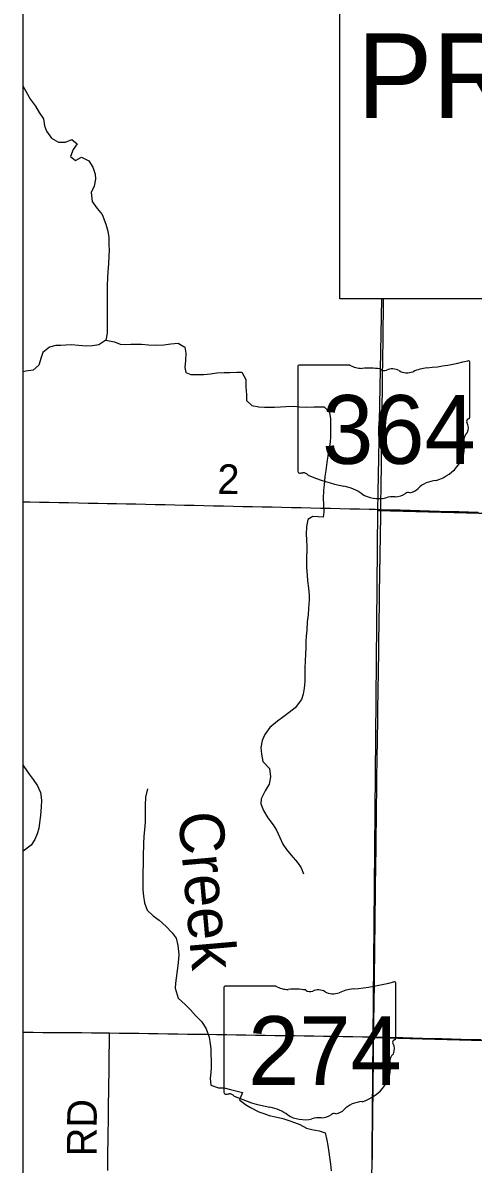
# Model space of a CAD drawing. Extents: x 0 to 34, y 0 to 22.
# Drawn here: x 2.1 to 2.963, y 17.239 to 19.428 of the extents above; entities that cross this region are included whole.
import ezdxf

# ---------------------------------------------------------------- set-up
doc = ezdxf.new("R2010")
doc.units = 0
for name, color, linetype in [('GM_X_Corporation', 7, 'Continuous'), ('GM_X_County_Road', 7, 'Continuous'), ('GM_X_County_Road_Text', 7, 'Continuous'), ('GM_X_Minor_River', 7, 'Continuous'), ('GM_X_Minor_River_Text', 7, 'Continuous'), ('GM_X_State_Location', 7, 'Continuous'), ('GM_X_State_Route', 7, 'Continuous'), ('GM_X_State_Shield', 7, 'Continuous'), ('GM_X_Township_Road', 7, 'Continuous'), ('GM_X_Township_Road_Text', 7, 'Continuous'), ('SH_Text', 7, 'Continuous')]:
    doc.layers.add(name, color=color, linetype=linetype)

msp = doc.modelspace()

# ---------------------------------------------------------------- linework, layer by layer
at = {"layer": 'GM_X_Corporation'}
for points in [[(8.9, 20.9), (2.1, 20.9), (2.1, 14.1), (7.7244, 14.1)], [(3.5996, 19.4692), (2.7976, 19.484), (2.7779, 19.4843), (2.1, 19.4964), (2.1, 16.485), (2.253, 16.4822), (2.4333, 16.478), (2.4403, 16.4778), (2.5826, 16.473), (2.7595, 16.4724), (3.1897, 16.4617), (3.4295, 16.4557), (3.687, 16.4502), (3.6948, 16.4501), (3.7682, 16.4494), (4.2697, 16.4379), (4.8738, 16.4249)], [(3.7979, 18.8986), (3.7969, 18.4658), (2.7802, 18.4929), (2.7874, 18.8986)]]:
    msp.add_lwpolyline(points, dxfattribs=at)
for points in [[(3.7969, 18.4658), (3.785, 17.4549), (2.771, 17.4824), (2.7802, 18.4929)], [(3.785, 17.4549), (3.7672, 16.4521), (2.7618, 16.4707), (2.771, 17.4824)]]:
    msp.add_lwpolyline(points, close=True, dxfattribs=at)
at = {"layer": 'GM_X_County_Road'}
msp.add_lwpolyline([(2.1, 18.5096), (2.1132, 18.5094), (2.1318, 18.509), (2.1504, 18.5086), (2.1691, 18.5082), (2.1877, 18.5079), (2.2063, 18.5075), (2.225, 18.5071), (2.2436, 18.5068), (2.2614, 18.5064), (2.2791, 18.5061), (2.2977, 18.5057), (2.3164, 18.5052), (2.335, 18.5048), (2.3537, 18.5044), (2.3723, 18.504), (2.3909, 18.5036), (2.4096, 18.5032), (2.4282, 18.5028), (2.4468, 18.5024), (2.4655, 18.502), (2.4841, 18.5016), (2.5027, 18.5011), (2.5214, 18.5007), (2.54, 18.5003), (2.5586, 18.4999), (2.5773, 18.4995), (2.5959, 18.4991), (2.6145, 18.4987), (2.6332, 18.4983), (2.6518, 18.4979), (2.6704, 18.4974), (2.6891, 18.497), (2.7077, 18.4966), (2.7263, 18.4962), (2.745, 18.4958), (2.7636, 18.4954), (2.7747, 18.4951), (2.7858, 18.4949), (2.8044, 18.4943), (2.823, 18.4938), (2.8417, 18.4933), (2.8603, 18.4927), (2.8789, 18.4922), (2.8976, 18.4916), (2.9162, 18.4911), (2.9349, 18.4906), (2.9535, 18.49), (2.9721, 18.4895)], dxfattribs=at)
at = {"layer": 'GM_X_Minor_River'}
for points in [[(2.1, 19.3067), (2.1065, 19.2954), (2.1145, 19.2808), (2.1241, 19.268), (2.1314, 19.2561), (2.1395, 19.2434), (2.1414, 19.23), (2.145, 19.2201), (2.1546, 19.2066), (2.1684, 19.199), (2.1817, 19.1987), (2.194, 19.2041), (2.204, 19.1959), (2.1962, 19.1847), (2.1913, 19.1712), (2.201, 19.1641), (2.2126, 19.1703), (2.2264, 19.1631), (2.2341, 19.1512), (2.2388, 19.1378), (2.2389, 19.1279), (2.2367, 19.1146), (2.2311, 19.1022), (2.2326, 19.0855), (2.2426, 19.072), (2.2518, 19.06), (2.259, 19.0419), (2.2625, 19.0282), (2.2645, 19.0164)], [(2.2645, 19.0164), (2.2649, 19.0019), (2.2651, 18.992), (2.2648, 18.9814), (2.2641, 18.9658), (2.2626, 18.9507), (2.262, 18.9389), (2.2613, 18.9249), (2.2613, 18.9085), (2.2614, 18.8964), (2.2614, 18.8796), (2.2616, 18.8698), (2.2617, 18.8572), (2.2614, 18.8458), (2.2615, 18.8329), (2.2589, 18.8193), (2.2458, 18.8101), (2.2333, 18.8085), (2.2219, 18.8076), (2.2064, 18.8091), (2.1935, 18.8101), (2.1825, 18.8096), (2.173, 18.8091), (2.1635, 18.8089), (2.1509, 18.8062), (2.1385, 18.7958), (2.1349, 18.786), (2.1308, 18.7717), (2.1199, 18.7617), (2.1059, 18.7601), (2.1, 18.7589)], [(2.2589, 18.8193), (2.2756, 18.8162), (2.2865, 18.8118), (2.2971, 18.8112), (2.3066, 18.8114), (2.3168, 18.8119), (2.327, 18.8116), (2.341, 18.8102), (2.3532, 18.8095), (2.3699, 18.8103), (2.3832, 18.8123), (2.3973, 18.8135), (2.4104, 18.8059), (2.412, 18.7941), (2.4113, 18.7801), (2.4103, 18.7672), (2.4119, 18.7576), (2.4217, 18.7536), (2.4316, 18.7534), (2.4464, 18.7538), (2.4597, 18.755), (2.4715, 18.7567), (2.4855, 18.7571), (2.4965, 18.7572), (2.5098, 18.7581), (2.5193, 18.7582), (2.527, 18.7436), (2.5274, 18.7299), (2.5282, 18.7143), (2.5283, 18.7037), (2.5388, 18.6943), (2.552, 18.6917), (2.5626, 18.6911), (2.5728, 18.6909), (2.5823, 18.691), (2.5933, 18.6916), (2.6039, 18.6921), (2.6191, 18.6925), (2.6301, 18.6915), (2.643, 18.6908), (2.6574, 18.6916), (2.6673, 18.6918), (2.6775, 18.6912), (2.6875, 18.6807), (2.6892, 18.6688), (2.6893, 18.6571), (2.6894, 18.6472), (2.6891, 18.6339), (2.6885, 18.624), (2.6859, 18.6096), (2.6845, 18.5975), (2.6824, 18.585), (2.6801, 18.5695), (2.6783, 18.5577), (2.6769, 18.5422), (2.6759, 18.5319), (2.6755, 18.5152), (2.676, 18.5057), (2.6765, 18.4901), (2.6755, 18.4802), (2.6656, 18.4805), (2.6558, 18.4811), (2.6458, 18.4752), (2.6436, 18.4616), (2.6429, 18.4472), (2.6434, 18.4365), (2.6439, 18.4239), (2.6432, 18.3951), (2.6434, 18.3833), (2.6445, 18.3688), (2.6454, 18.3581), (2.647, 18.3437), (2.6483, 18.3307), (2.6484, 18.3208), (2.6473, 18.3053), (2.6463, 18.2927), (2.6448, 18.2791), (2.6437, 18.2631), (2.6427, 18.2517), (2.6421, 18.2415), (2.6418, 18.2282), (2.6412, 18.2183), (2.6409, 18.2031), (2.6402, 18.1914), (2.6399, 18.1777), (2.64, 18.1647), (2.639, 18.1518), (2.6372, 18.1408), (2.634, 18.1303), (2.6215, 18.1146), (2.6099, 18.1054), (2.6002, 18.0976), (2.5879, 18.0887), (2.5732, 18.0769), (2.5638, 18.0631), (2.5583, 18.0518), (2.5561, 18.0385), (2.5573, 18.0256), (2.5596, 18.0114), (2.5726, 17.9982), (2.5745, 17.9818)], [(2.1, 18.0053), (2.1016, 18.0021), (2.1122, 17.9874), (2.1196, 17.977), (2.1281, 17.965), (2.1339, 17.9523), (2.1358, 17.9375), (2.1351, 17.9245), (2.1336, 17.9082), (2.1318, 17.8938), (2.1304, 17.8832), (2.1276, 17.873), (2.1231, 17.8617), (2.1157, 17.8508), (2.1006, 17.8394), (2.1, 17.839)], [(2.5745, 17.9818), (2.572, 17.9682), (2.5641, 17.955), (2.5565, 17.9396), (2.5556, 17.9301), (2.561, 17.9175), (2.5694, 17.9036), (2.5797, 17.89), (2.5856, 17.8796), (2.5925, 17.8658), (2.5979, 17.8531), (2.6052, 17.8427), (2.6141, 17.8318), (2.6259, 17.8179), (2.6329, 17.8078), (2.6376, 17.7959)], [(2.3385, 17.9591), (2.3347, 17.9428), (2.3344, 17.9272), (2.3344, 17.912), (2.334, 17.8949), (2.3329, 17.8805), (2.3319, 17.8683), (2.3308, 17.8535), (2.3303, 17.8299), (2.3305, 17.8197), (2.3299, 17.7938), (2.3299, 17.7782), (2.33, 17.7653), (2.3309, 17.7531), (2.3333, 17.7405), (2.3383, 17.7267), (2.3494, 17.7158), (2.361, 17.7075), (2.3748, 17.6954), (2.3859, 17.683), (2.3936, 17.6726), (2.3967, 17.6588), (2.3986, 17.6413), (2.3975, 17.6253), (2.3953, 17.6105), (2.3934, 17.5961), (2.3925, 17.5866), (2.3919, 17.5768), (2.3975, 17.5576), (2.4109, 17.5455), (2.4213, 17.5354), (2.4306, 17.5245), (2.4428, 17.5121), (2.4509, 17.499), (2.457, 17.4832), (2.459, 17.4702), (2.4599, 17.4607), (2.4604, 17.4501), (2.4609, 17.4379), (2.461, 17.4249), (2.46, 17.4151), (2.459, 17.4037), (2.4602, 17.3911), (2.4745, 17.3858), (2.4859, 17.3856), (2.4976, 17.3823), (2.5108, 17.3793), (2.521, 17.3768), (2.515, 17.3629), (2.5262, 17.3538), (2.5363, 17.3479), (2.5521, 17.3399), (2.5618, 17.3363), (2.5716, 17.333), (2.5837, 17.3301), (2.5977, 17.3271), (2.6097, 17.323), (2.6203, 17.3194), (2.6304, 17.3153), (2.6432, 17.3086), (2.6533, 17.3057), (2.6673, 17.3031), (2.679, 17.2994), (2.6825, 17.2856), (2.6841, 17.2749), (2.6862, 17.2627), (2.6875, 17.2528), (2.6891, 17.2395), (2.6903, 17.2265)]]:
    msp.add_lwpolyline(points, dxfattribs=at)
at = {"layer": 'GM_X_State_Route'}
for points in [[(2.7694, 17.2383), (2.7696, 17.257), (2.7698, 17.2756), (2.77, 17.2943), (2.7702, 17.3129), (2.7704, 17.3315), (2.7706, 17.3502), (2.7708, 17.3688), (2.771, 17.3875), (2.7712, 17.4061), (2.7715, 17.4248), (2.7717, 17.4434), (2.7719, 17.462), (2.772, 17.4728), (2.7721, 17.4835), (2.7723, 17.5021), (2.7726, 17.5208), (2.7728, 17.5394), (2.773, 17.5581), (2.7733, 17.5767), (2.7735, 17.5953), (2.7737, 17.614), (2.774, 17.6326), (2.7742, 17.6513), (2.7744, 17.6699), (2.7746, 17.6885), (2.7749, 17.7072), (2.7751, 17.7258), (2.7753, 17.7445), (2.7756, 17.7631), (2.7758, 17.7818), (2.776, 17.8004), (2.7763, 17.819), (2.7765, 17.8377), (2.7767, 17.8563), (2.7769, 17.875), (2.7772, 17.8936), (2.7774, 17.9122), (2.7776, 17.9309), (2.7778, 17.9495), (2.7781, 17.9682), (2.7782, 17.9785), (2.7783, 17.9887), (2.7786, 18.0074), (2.7789, 18.026), (2.7791, 18.0447), (2.7794, 18.0633), (2.7797, 18.082), (2.78, 18.1006), (2.7802, 18.1192), (2.7805, 18.1379), (2.7808, 18.1565), (2.7811, 18.1752), (2.7813, 18.1938), (2.7816, 18.2124), (2.7819, 18.2311), (2.7822, 18.2497), (2.7824, 18.2684), (2.7827, 18.287), (2.783, 18.3056), (2.7832, 18.3243), (2.7835, 18.3429), (2.7838, 18.3616), (2.7841, 18.3802), (2.7843, 18.3988), (2.7846, 18.4175), (2.7849, 18.4361), (2.7852, 18.4548), (2.7855, 18.4734), (2.7856, 18.4842), (2.7858, 18.4949), (2.786, 18.5135), (2.7863, 18.5322), (2.7865, 18.5508), (2.7867, 18.5695), (2.787, 18.5881), (2.7872, 18.6067), (2.7875, 18.6254), (2.7877, 18.644), (2.788, 18.6627), (2.7882, 18.6813), (2.7884, 18.6999), (2.7887, 18.7186), (2.7889, 18.7372), (2.7892, 18.7559), (2.7894, 18.7745), (2.7896, 18.7931), (2.7899, 18.8118), (2.7901, 18.8304), (2.7904, 18.8491), (2.7906, 18.8677), (2.7908, 18.8864), (2.791, 18.8986)], [(2.1, 17.4923), (2.1013, 17.4923), (2.12, 17.4922), (2.1386, 17.492), (2.1572, 17.4919), (2.1759, 17.4918), (2.1945, 17.4917), (2.2132, 17.4916), (2.2318, 17.4914), (2.249, 17.4913), (2.2661, 17.4912), (2.2847, 17.4909), (2.3034, 17.4906), (2.322, 17.4904), (2.3407, 17.4901), (2.3593, 17.4898), (2.378, 17.4895), (2.3966, 17.4892), (2.4152, 17.4889), (2.4339, 17.4886), (2.4525, 17.4884), (2.4712, 17.4881), (2.4898, 17.4878), (2.5084, 17.4875), (2.5271, 17.4872), (2.5457, 17.4869), (2.5644, 17.4866), (2.583, 17.4864), (2.6016, 17.4861), (2.6203, 17.4858), (2.6389, 17.4855), (2.6576, 17.4852), (2.6762, 17.485), (2.6949, 17.4847), (2.7135, 17.4844), (2.7321, 17.4841), (2.7508, 17.4838), (2.7614, 17.4837), (2.7721, 17.4835), (2.7907, 17.483), (2.8094, 17.4825), (2.828, 17.482), (2.8467, 17.4816), (2.8653, 17.4811), (2.8839, 17.4806), (2.9026, 17.4801), (2.9212, 17.4796), (2.9398, 17.4791), (2.9585, 17.4787), (2.9771, 17.4782)]]:
    msp.add_lwpolyline(points, dxfattribs=at)
at = {"layer": 'GM_X_State_Shield'}
for p, q in [((2.9563, 18.6719), (2.9563, 18.7766)), ((2.6267, 18.7682), (2.6267, 18.5681)), ((2.7265, 18.7716), (2.63, 18.7716)), ((2.9563, 18.6719), (2.9563, 18.6719)), ((2.4851, 17.5774), (2.4851, 17.3772)), ((2.5848, 17.5808), (2.4883, 17.5808)), ((2.8147, 17.4811), (2.8147, 17.5858)), ((2.8146, 17.4811), (2.8147, 17.4811))]:
    msp.add_line(p, q, dxfattribs=at)
for centre, major_axis, start_param, end_param in [((2.8389, 19.0445), (0.3495, 0), 4.814394, 5.042369), ((2.9527, 18.777), (0.00367, 0), 6.141152, 7.989035), ((2.6305, 18.7686), (0.00382, 0), 1.712693, 3.28349), ((2.7495, 18.7949), (0.037, 0), 4.042523, 4.731795), ((2.7618, 18.6593), (0.133, 0), 1.404758, 1.657858), ((2.7919, 18.7697), (0.0107, 0), 3.836095, 5.185415), ((2.8076, 18.7465), (0.0222, 0), 0.950623, 2.079405), ((2.8363, 18.7782), (0.0267, 0), 4.081561, 5.145723), ((2.8835, 18.7105), (0.0703, 0), 1.699011, 2.107814), ((2.9555, 18.6642), (0.00568, 0), 1.883978, 3.671073), ((2.9524, 18.6715), (0.00393, 0), 5.05454, 6.418171), ((2.9193, 18.651), (0.0341, 0), 5.934695, 6.695948), ((2.8585, 18.6148), (0.0874, 0), 5.101752, 6.440018), ((2.9695, 18.6281), (0.0248, 0), 2.387724, 3.262537), ((2.6305, 18.5676), (0.00385, 0), 3.00124, 4.508301), ((2.6311, 18.5881), (0.0294, 0), 4.665946, 4.897461), ((2.6371, 18.5565), (0.0106, 0), 0.519207, 1.627899), ((2.771, 18.7363), (0.2524, 0), 4.195997, 4.488961), ((2.6957, 18.4782), (0.079, 0), 0.823519, 1.323587), ((2.8954, 18.5119), (0.0479, 0), 1.647645, 2.488434), ((2.7811, 18.5555), (0.0501, 0), 4.026481, 4.996735), ((2.8101, 18.4863), (0.0412, 0), 1.495662, 1.94098), ((2.8137, 18.5405), (0.0267, 0), 4.691044, 5.507374), ((2.8379, 18.5212), (0.00752, 0), 1.147584, 2.315152), ((2.8347, 18.5487), (0.0282, 0), 4.937069, 5.64225), ((2.4888, 17.5778), (0.00382, 0), 1.712693, 3.28349), ((2.6078, 17.604), (0.037, 0), 4.042523, 4.731795), ((2.6201, 17.4685), (0.133, 0), 1.404758, 1.657858), ((2.6503, 17.5788), (0.0107, 0), 3.836095, 5.185415), ((2.666, 17.5557), (0.0222, 0), 0.950623, 2.079405), ((2.7418, 17.5197), (0.0703, 0), 1.699011, 2.107814), ((2.6972, 17.8536), (0.3495, 0), 4.814394, 5.042369), ((2.811, 17.5862), (0.00367, 0), 6.141152, 7.989035), ((2.6946, 17.5874), (0.0267, 0), 4.081561, 5.145723), ((2.8138, 17.4734), (0.00568, 0), 1.883978, 3.671073), ((2.7777, 17.4602), (0.0341, 0), 5.934695, 6.695948), ((2.8107, 17.4807), (0.00393, 0), 5.05454, 6.418171), ((2.8278, 17.4373), (0.0248, 0), 2.387724, 3.262537), ((2.7168, 17.4239), (0.0874, 0), 5.101752, 6.440018), ((2.4889, 17.3768), (0.00385, 0), 3.00124, 4.508301), ((2.4895, 17.3973), (0.0294, 0), 4.665946, 4.897461), ((2.4955, 17.3657), (0.0106, 0), 0.519207, 1.627899), ((2.6293, 17.5455), (0.2524, 0), 4.195997, 4.488961), ((2.7537, 17.3211), (0.0479, 0), 1.647645, 2.488434), ((2.5541, 17.2873), (0.079, 0), 0.823519, 1.323587), ((2.6395, 17.3647), (0.0501, 0), 4.026481, 4.996735), ((2.6721, 17.3497), (0.0267, 0), 4.691044, 5.507374), ((2.6962, 17.3303), (0.00752, 0), 1.147584, 2.315152), ((2.693, 17.3578), (0.0282, 0), 4.937069, 5.64225), ((2.6684, 17.2955), (0.0412, 0), 1.495662, 1.94098)]:
    msp.add_ellipse(centre, major_axis=major_axis, ratio=0.8, start_param=start_param, end_param=end_param, dxfattribs=at)
at = {"layer": 'GM_X_Township_Road'}
msp.add_lwpolyline([(2.2626, 17.2271), (2.2629, 17.2457), (2.2631, 17.2644), (2.2634, 17.283), (2.2636, 17.3016), (2.2639, 17.3203), (2.2641, 17.3389), (2.2643, 17.3576), (2.2646, 17.3762), (2.2648, 17.3948), (2.2651, 17.4135), (2.2653, 17.4321), (2.2656, 17.4508), (2.2658, 17.4694), (2.266, 17.4803), (2.2661, 17.4912)], dxfattribs=at)
at = {"layer": 'SH_Text'}
msp.add_lwpolyline([(2.7075, 19.4692), (4.7562, 19.4692), (4.7562, 18.8986), (2.7075, 18.8986)], close=True, dxfattribs=at)

# ---------------------------------------------------------------- texts
at = {"layer": 'GM_X_County_Road_Text'}
msp.add_text('2', height=0.0568, rotation=358.8989, dxfattribs=at).set_placement((2.4722, 18.5248))
at = {"layer": 'GM_X_Minor_River_Text'}
msp.add_text('Creek', height=0.08523, rotation=275.0626, dxfattribs=at).set_placement((2.3974, 17.9122))
at = {"layer": 'GM_X_State_Location'}
for s, p in [('s', (2.7878, 18.6548)), ('r', (2.7878, 18.6548)), ('s', (2.6462, 17.464)), ('r', (2.6461, 17.464))]:
    msp.add_text(s, height=0.000189, dxfattribs=at).set_placement(p)
for s, p in [('364', (2.721, 18.641)), ('274', (2.5793, 17.4502))]:
    msp.add_text(s, height=0.000189, rotation=0, dxfattribs=at).set_placement(p)
at = {"layer": 'GM_X_State_Shield'}
for s, p in [('364', (2.6733, 18.5822)), ('274', (2.5316, 17.3913))]:
    msp.add_text(s, height=0.13184, dxfattribs=at).set_placement(p)
at = {"layer": 'GM_X_Township_Road_Text'}
msp.add_text('RD', height=0.05682, rotation=89.5063, dxfattribs=at).set_placement((2.2411, 17.2543))
at = {"layer": 'SH_Text'}
msp.add_text('PROJECT LOCATION', height=0.162, dxfattribs=at).set_placement((2.74, 19.2454))

doc.saveas('drawing.dxf')
